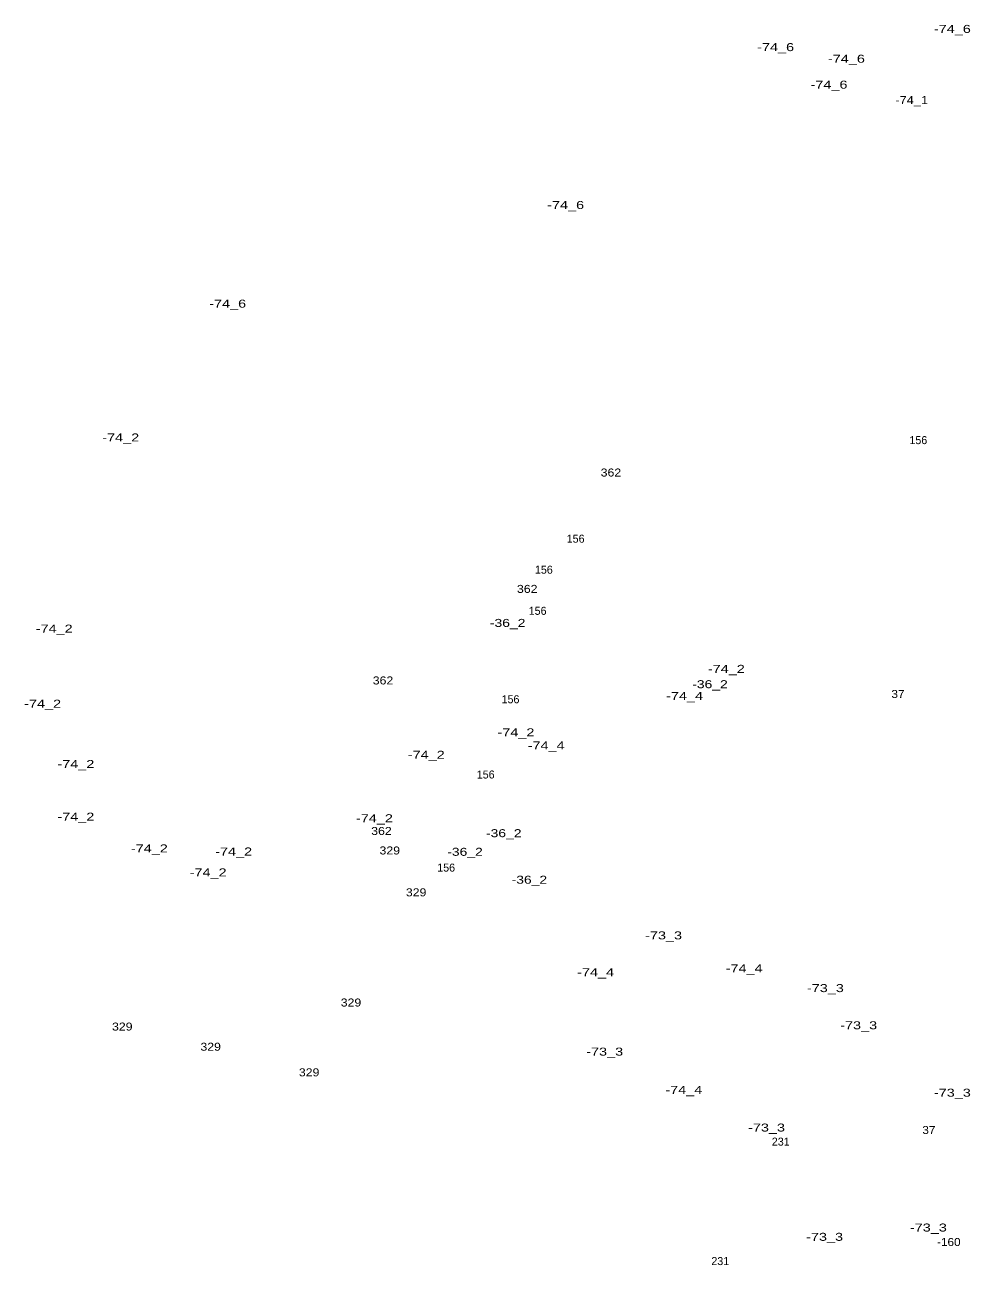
# Model space of a CAD drawing. Extents: x -658110 to -655750, y -1000429 to -997657.
# Drawn here: x -658110 to -657637, y -999740 to -999120 of the extents above; entities that cross this region are included whole.
import ezdxf
from ezdxf.enums import TextEntityAlignment as Align

# ---------------------------------------------------------------- set-up
doc = ezdxf.new("R2010")
doc.units = 0
doc.header["$LTSCALE"] = 1.6
doc.layers.add('24', color=7, linetype='Continuous')

msp = doc.modelspace()

# ---------------------------------------------------------------- texts
at = {"layer": '24'}
for s, width, p in [('-74_6', 1.35, (-657646.181, -999124.07)), ('-74_6', 1.35, (-657734.561, -999133.17)), ('-74_6', 1.35, (-657699.171, -999138.97)), ('-74_6', 1.35, (-657707.87, -999151.93)), ('-74_1', 1.2, (-657666.53, -999159.65)), ('-74_6', 1.35, (-657839.581, -999212.1)), ('-74_6', 1.35, (-658008.611, -999261.43)), ('-74_2', 1.35, (-658062.09, -999328.32)), ('362', 1.15, (-657816.93, -999345.85)), ('362', 1.15, (-657858.8, -999404.03)), ('-36_2', 1.3, (-657868.59, -999421.04)), ('-74_2', 1.35, (-658095.35, -999423.88)), ('-74_2', 1.35, (-657759.22, -999444.01)), ('362', 1.15, (-657930.92, -999449.8)), ('-36_2', 1.3, (-657767.39, -999451.68)), ('-74_4', 1.35, (-657780.11, -999457.56)), ('37', 1.1, (-657673.38, -999456.57)), ('-74_2', 1.35, (-658101.15, -999461.43)), ('-74_2', 1.35, (-657864.429, -999475.74)), ('-74_4', 1.35, (-657849.34, -999482.32)), ('-74_2', 1.35, (-657909.299, -999486.96)), ('-74_2', 1.35, (-658084.52, -999491.59)), ('-74_2', 1.35, (-658084.52, -999517.9)), ('-74_2', 1.35, (-657935.209, -999518.69)), ('362', 1.15, (-657931.7, -999525.05)), ('-36_2', 1.3, (-657870.53, -999526.16)), ('-74_2', 1.35, (-658047.77, -999533.78)), ('-74_2', 1.35, (-658005.61, -999535.32)), ('329', 1.15, (-657927.54, -999534.8)), ('-36_2', 1.3, (-657889.91, -999535.47)), ('-74_2', 1.35, (-658018.37, -999545.77)), ('-36_2', 1.3, (-657857.73, -999549.43)), ('329', 1.15, (-657914.36, -999555.74)), ('-73_3', 1.35, (-657790.62, -999577.26)), ('-74_4', 1.35, (-657750.319, -999593.74)), ('-74_4', 1.35, (-657824.59, -999595.68)), ('-73_3', 1.35, (-657709.68, -999603.61)), ('329', 1.15, (-657946.93, -999610.82)), ('329', 1.15, (-658061.31, -999622.85)), ('-73_3', 1.35, (-657693.04, -999622.2)), ('329', 1.15, (-658017.11, -999632.93)), ('-73_3', 1.35, (-657820.06, -999635.37)), ('329', 1.15, (-657967.87, -999645.73)), ('-74_4', 1.35, (-657780.49, -999654.49)), ('-73_3', 1.35, (-657646.18, -999655.91)), ('-73_3', 1.35, (-657739.12, -999673.34)), ('37', 1.1, (-657657.92, -999674.55)), ('-73_3', 1.35, (-657658.18, -999723.32)), ('-73_3', 1.35, (-657710.08, -999727.97)), ('-160', 1.1, (-657647.96, -999730.56))]:
    msp.add_text(s, height=4, dxfattribs=dict(at, width=width)).set_placement(p, align=Align.CENTER)
for s, p in [('156', (-657663.201, -999329.65)), ('156', (-657834.591, -999378.92)), ('156', (-657850.49, -999394.43)), ('156', (-657853.591, -999414.99)), ('156', (-657867.16, -999459.21)), ('156', (-657879.571, -999496.83)), ('156', (-657899.341, -999543.38)), ('231', (-657732.01, -999680.36)), ('231', (-657762.26, -999740.09))]:
    msp.add_text(s, height=4, dxfattribs=at).set_placement(p, align=Align.CENTER)

doc.saveas('drawing.dxf')
